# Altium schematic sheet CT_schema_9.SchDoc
size 278 x 170 mm
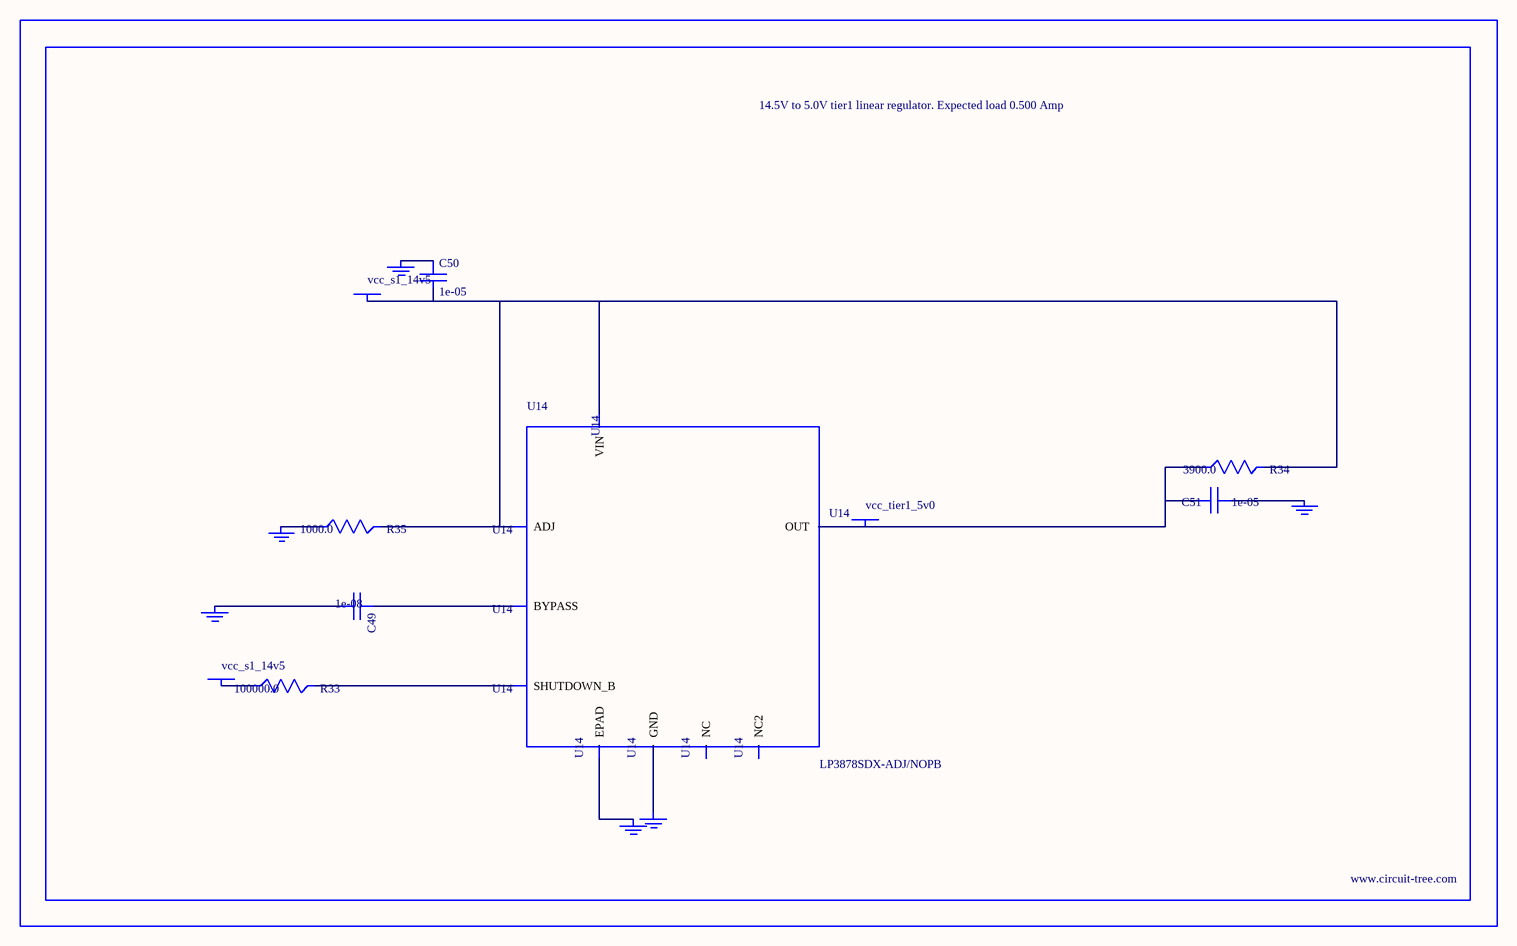
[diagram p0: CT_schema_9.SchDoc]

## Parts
BORDER8  (no value)
C49  1e-08  [C0402]
C50  1e-05  [C1210]
C51  1e-05  [C1210]
GND_INSTANCE_8_0  (no value)
GND_INSTANCE_8_1  (no value)
GND_INSTANCE_8_2  (no value)
GND_INSTANCE_8_3  (no value)
GND_INSTANCE_8_4  (no value)
GND_INSTANCE_8_5  (no value)
POWER_INSTANCE_8_0  vcc_s1_14v5
POWER_INSTANCE_8_1  vcc_s1_14v5
POWER_INSTANCE_8_2  vcc_tier1_5v0
R33  100000.0  [R0603]
R34  3900.0  [R0603]
R35  1000.0  [R0603]
U14  LP3878SDX-ADJ/NOPB  [WSON-8]

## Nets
NetC49_1: C49.1 U14.1(BYPASS)
NetC49_2: C49.2 GND_INSTANCE_8_0.0(GND)
NetC50_1: C50.1 GND_INSTANCE_8_1.0(GND)
NetC50_2: C50.2 POWER_INSTANCE_8_0.0(PWR) R34.2 R35.2 U14.4(VIN) U14.6(ADJ)
NetC51_1: C51.1 GND_INSTANCE_8_2.0(GND)
NetC51_2: C51.2 POWER_INSTANCE_8_2.0(PWR) R34.1 U14.5(OUT)
NetGND_INSTANCE_8_3_0: GND_INSTANCE_8_3.0(GND) R35.1
NetGND_INSTANCE_8_4_0: GND_INSTANCE_8_4.0(GND) U14.PAD(EPAD)
NetGND_INSTANCE_8_5_0: GND_INSTANCE_8_5.0(GND) U14.3(GND)
NetPOWER_INSTANCE_8_1_0: POWER_INSTANCE_8_1.0(PWR) R33.1
NetR33_2: R33.2 U14.8(SHUTDOWN_B)

Not connected (* = marked no-connect by the designer): U14 2(NC) 7(NC2)

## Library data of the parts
BORDER8 = BORDER_PAGE8
C49 = C0402C103K3RAC
C50 = C1210C106K5PACTU
C51 = GRM32DR61E106MA12L
GND_INSTANCE_8_0-GND_INSTANCE_8_5 = GND
POWER_INSTANCE_8_0-POWER_INSTANCE_8_2 = PWR
R33 = RC0603JR-07100KL
R34 = RC0603JR-073K9L
R35 = RC0603JR-071KL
